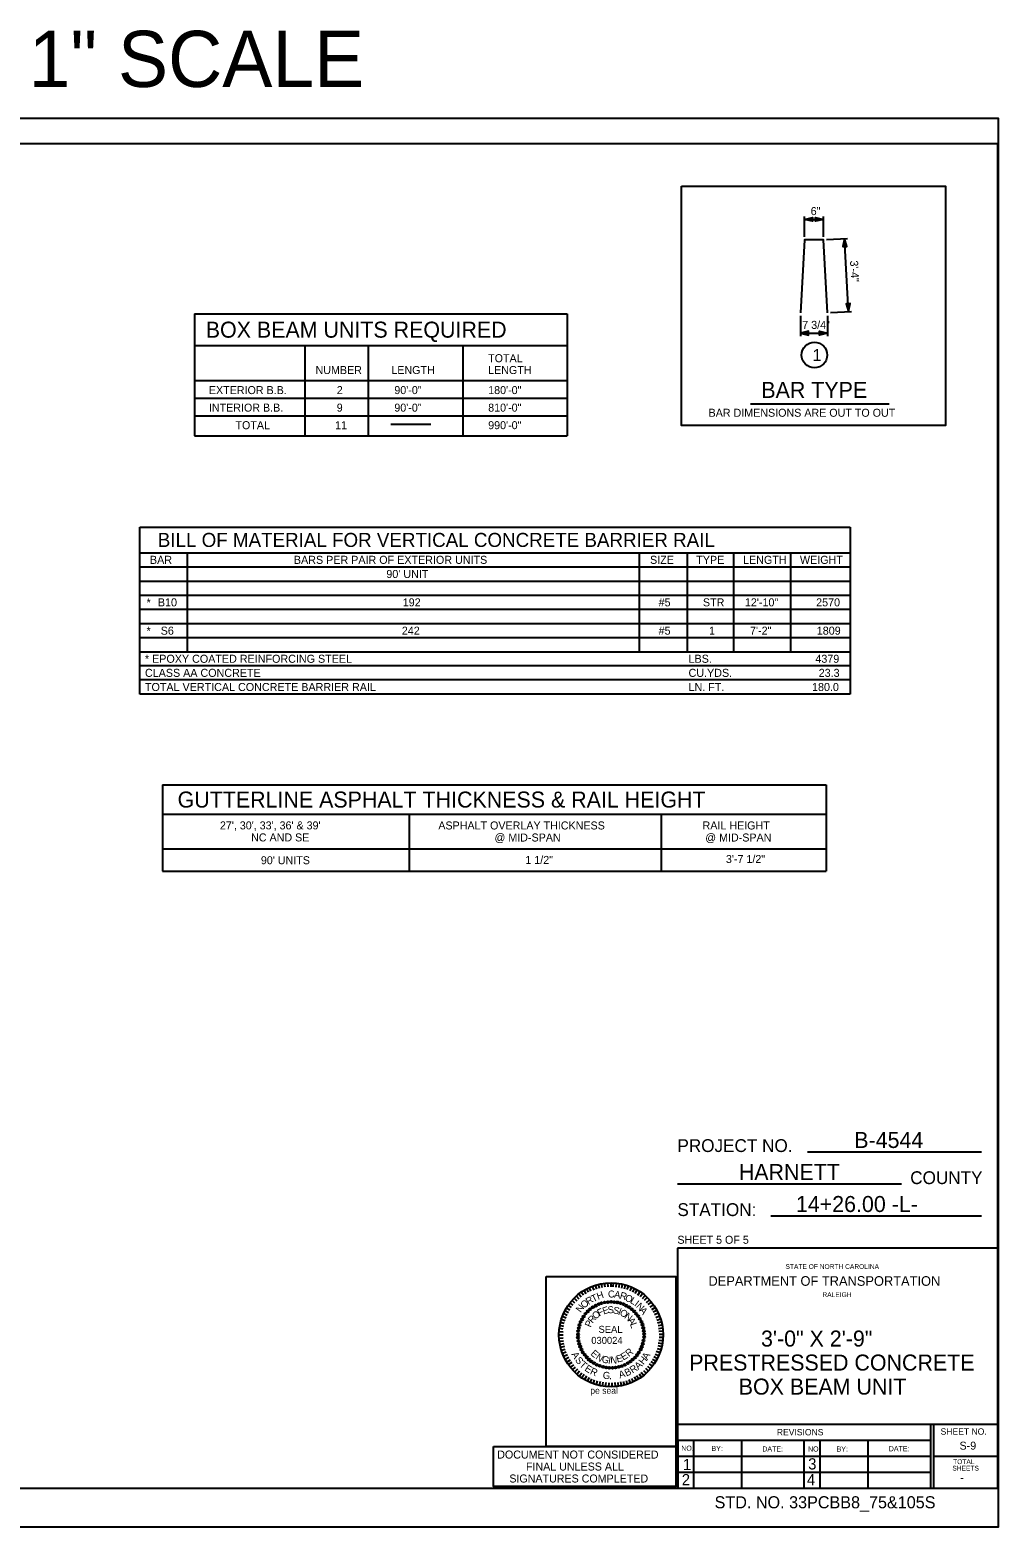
# Model space of a CAD drawing. Extents: x -38 to 94, y -165 to 80.
# Drawn here: x 72.87 to 88, y -165.04 to -141.66 of the extents above; entities that cross this region are included whole.
import ezdxf

# ---------------------------------------------------------------- set-up
doc = ezdxf.new("R2010")
doc.units = 0
for name, color, linetype in [('Arrowhead Terminators', 7, 'Continuous'), ('Arrowhead Terminators CELL', 7, 'Continuous'), ('Dimension Lines', 7, 'Continuous'), ('Peseal', 7, 'Continuous'), ('Plan Sheet', 7, 'Continuous'), ('Plan Sheet CELL', 7, 'Continuous'), ('Plot Shape CELL', 7, 'Continuous'), ('Rebar Lines', 7, 'Continuous'), ('Sheet Sticker Exception Certification CELL', 7, 'Continuous'), ('Subtitle Text', 7, 'Continuous'), ('Text', 7, 'Continuous'), ('Title Text', 7, 'Continuous'), ('User Information Notes', 7, 'Continuous'), ('User Information Notes CELL', 7, 'Continuous')]:
    doc.layers.add(name, color=color, linetype=linetype)

msp = doc.modelspace()

# ---------------------------------------------------------------- linework, layer by layer
at = {"layer": 'Arrowhead Terminators'}
for points in [[(84.973, -144.616), (85.098, -144.585), (85.098, -144.647)], [(85.27, -144.616), (85.145, -144.647), (85.145, -144.585)], [(84.911, -146.393), (85.036, -146.425), (85.036, -146.362)], [(85.333, -146.393), (85.208, -146.425), (85.208, -146.362)]]:
    msp.add_lwpolyline(points, close=True, dxfattribs=at)
at = {"layer": 'Arrowhead Terminators CELL'}
for points in [[(85.596, -144.916), (85.572, -145.042), (85.634, -145.039)], [(85.659, -146.056), (85.683, -145.93), (85.621, -145.933)]]:
    msp.add_lwpolyline(points, close=True, dxfattribs=at)
at = {"layer": 'Dimension Lines'}
for p, q in [((84.973, -144.888), (84.973, -144.571)), ((84.973, -144.616), (85.27, -144.616)), ((85.27, -144.888), (85.27, -144.571)), ((85.316, -144.931), (85.642, -144.913)), ((85.659, -146.056), (85.596, -144.916)), ((85.379, -146.072), (85.705, -146.054)), ((84.911, -146.122), (84.911, -146.439)), ((85.333, -146.122), (85.333, -146.439)), ((84.911, -146.393), (85.333, -146.393))]:
    msp.add_line(p, q, dxfattribs=at)
at = {"layer": 'Peseal'}
for p, q in [((81.598, -161.372), (81.571, -161.318)), ((81.637, -161.353), (81.614, -161.298)), ((81.684, -161.337), (81.661, -161.279)), ((81.727, -161.321), (81.708, -161.259)), ((81.77, -161.31), (81.755, -161.247)), ((81.813, -161.298), (81.801, -161.236)), ((81.856, -161.294), (81.848, -161.232)), ((81.903, -161.286), (81.899, -161.224)), ((81.95, -161.286), (81.95, -161.224)), ((81.985, -161.286), (81.989, -161.224)), ((82.028, -161.29), (82.036, -161.228)), ((82.075, -161.298), (82.083, -161.236)), ((82.118, -161.306), (82.13, -161.243)), ((82.161, -161.318), (82.176, -161.255)), ((82.204, -161.329), (82.227, -161.271)), ((82.247, -161.349), (82.274, -161.29)), ((82.29, -161.368), (82.317, -161.31)), ((81.356, -161.575), (81.309, -161.54)), ((81.387, -161.54), (81.341, -161.501)), ((81.419, -161.509), (81.372, -161.462)), ((81.45, -161.478), (81.411, -161.431)), ((81.485, -161.446), (81.446, -161.4)), ((81.52, -161.419), (81.485, -161.368)), ((81.559, -161.396), (81.528, -161.341)), ((82.329, -161.388), (82.36, -161.333)), ((82.368, -161.415), (82.403, -161.361)), ((82.403, -161.439), (82.442, -161.392)), ((82.442, -161.47), (82.481, -161.423)), ((82.473, -161.497), (82.516, -161.454)), ((82.505, -161.532), (82.551, -161.489)), ((82.532, -161.564), (82.583, -161.525)), ((81.247, -161.775), (81.188, -161.751)), ((81.266, -161.732), (81.208, -161.704)), ((81.286, -161.693), (81.227, -161.661)), ((81.305, -161.65), (81.251, -161.618)), ((81.333, -161.611), (81.278, -161.575)), ((82.563, -161.603), (82.614, -161.568)), ((82.587, -161.638), (82.637, -161.607)), ((82.61, -161.677), (82.665, -161.65)), ((82.63, -161.72), (82.684, -161.693)), ((82.649, -161.763), (82.708, -161.739)), ((81.2, -161.993), (81.137, -161.989)), ((81.204, -161.947), (81.145, -161.939)), ((81.212, -161.904), (81.149, -161.892)), ((81.219, -161.861), (81.161, -161.845)), ((81.231, -161.818), (81.173, -161.798)), ((82.665, -161.806), (82.723, -161.786)), ((82.676, -161.849), (82.735, -161.833)), ((82.684, -161.892), (82.747, -161.88)), ((82.692, -161.935), (82.755, -161.927)), ((82.696, -161.978), (82.759, -161.974)), ((81.2, -162.04), (81.137, -162.04)), ((81.2, -162.087), (81.137, -162.091)), ((81.208, -162.134), (81.145, -162.142)), ((81.212, -162.177), (81.153, -162.189)), ((81.223, -162.22), (81.161, -162.236)), ((82.669, -162.247), (82.731, -162.267)), ((82.68, -162.204), (82.743, -162.22)), ((82.688, -162.161), (82.751, -162.173)), ((82.696, -162.118), (82.759, -162.126)), ((82.7, -162.025), (82.762, -162.025)), ((82.7, -162.072), (82.762, -162.075)), ((81.235, -162.263), (81.176, -162.282)), ((81.251, -162.306), (81.192, -162.329)), ((81.27, -162.349), (81.212, -162.376)), ((81.29, -162.388), (81.231, -162.419)), ((81.313, -162.431), (81.259, -162.462)), ((81.337, -162.466), (81.286, -162.501)), ((82.571, -162.454), (82.626, -162.489)), ((82.598, -162.415), (82.653, -162.447)), ((82.618, -162.376), (82.676, -162.404)), ((82.637, -162.337), (82.696, -162.361)), ((82.657, -162.29), (82.716, -162.314)), ((81.364, -162.505), (81.313, -162.544)), ((81.391, -162.54), (81.348, -162.579)), ((81.426, -162.572), (81.38, -162.618)), ((81.458, -162.603), (81.419, -162.65)), ((81.493, -162.634), (81.458, -162.681)), ((81.528, -162.657), (81.493, -162.708)), ((81.567, -162.681), (81.536, -162.736)), ((81.606, -162.704), (81.579, -162.759)), ((82.27, -162.716), (82.298, -162.771)), ((82.309, -162.693), (82.341, -162.751)), ((82.348, -162.669), (82.384, -162.724)), ((82.387, -162.646), (82.423, -162.697)), ((82.423, -162.618), (82.462, -162.669)), ((82.458, -162.591), (82.497, -162.634)), ((82.489, -162.556), (82.536, -162.603)), ((82.52, -162.525), (82.567, -162.568)), ((82.548, -162.489), (82.598, -162.529)), ((81.645, -162.724), (81.622, -162.779)), ((81.688, -162.739), (81.669, -162.798)), ((81.735, -162.755), (81.716, -162.814)), ((81.778, -162.767), (81.762, -162.825)), ((81.821, -162.775), (81.809, -162.837)), ((81.868, -162.782), (81.86, -162.845)), ((81.915, -162.786), (81.911, -162.849)), ((81.962, -162.786), (81.962, -162.849)), ((82.009, -162.782), (82.012, -162.845)), ((82.055, -162.779), (82.063, -162.841)), ((82.098, -162.771), (82.11, -162.833)), ((82.141, -162.763), (82.157, -162.822)), ((82.184, -162.747), (82.204, -162.81)), ((82.227, -162.732), (82.251, -162.79))]:
    msp.add_line(p, q, dxfattribs=at)
for centre, radius in [((81.757, -161.558), 0.0149), ((81.801, -161.542), 0.0142), ((81.85, -161.53), 0.0138), ((81.901, -161.525), 0.0157), ((81.95, -161.521), 0.0156), ((81.999, -161.525), 0.0157), ((82.048, -161.529), 0.0161), ((82.098, -161.542), 0.0142), ((82.143, -161.558), 0.0149), ((81.499, -161.794), 0.018), ((81.522, -161.749), 0.0168), ((81.55, -161.706), 0.0138), ((81.587, -161.669), 0.0166), ((81.624, -161.636), 0.0168), ((81.667, -161.605), 0.0168), ((81.712, -161.579), 0.0175), ((82.188, -161.581), 0.0157), ((82.231, -161.605), 0.0157), ((82.272, -161.634), 0.0153), ((82.311, -161.669), 0.0153), ((82.344, -161.706), 0.0153), ((82.374, -161.743), 0.0157), ((82.401, -161.786), 0.0157), ((81.434, -162.029), 0.0156), ((81.438, -161.98), 0.0157), ((81.446, -161.931), 0.0161), ((81.458, -161.882), 0.0167), ((81.475, -161.835), 0.0149), ((82.425, -161.831), 0.0149), ((82.442, -161.878), 0.0167), ((82.454, -161.927), 0.0161), ((82.462, -161.976), 0.0157), ((82.466, -162.025), 0.0156), ((81.434, -162.077), 0.0157), ((81.442, -162.128), 0.0157), ((81.454, -162.177), 0.0161), ((81.469, -162.222), 0.0167), ((81.489, -162.267), 0.0175), ((82.413, -162.263), 0.0157), ((82.43, -162.222), 0.0167), ((82.446, -162.173), 0.0161), ((82.458, -162.124), 0.0157), ((82.466, -162.073), 0.0157), ((81.51, -162.31), 0.0157), ((81.54, -162.347), 0.0153), ((81.571, -162.388), 0.0166), ((81.606, -162.423), 0.0166), ((81.643, -162.452), 0.0168), ((81.684, -162.48), 0.0157), ((82.212, -162.48), 0.0157), ((82.253, -162.454), 0.0153), ((82.288, -162.423), 0.0153), ((82.325, -162.39), 0.0153), ((82.358, -162.351), 0.0168), ((82.385, -162.31), 0.0157), ((81.729, -162.503), 0.0149), ((81.776, -162.521), 0.0167), ((81.825, -162.536), 0.0161), ((81.874, -162.548), 0.0157), ((81.923, -162.552), 0.0156), ((81.973, -162.552), 0.0156), ((82.022, -162.548), 0.0157), ((82.071, -162.536), 0.0161), ((82.12, -162.523), 0.0149), ((82.165, -162.505), 0.0175)]:
    msp.add_circle(centre, radius, dxfattribs=at)
at = {"layer": 'Plan Sheet'}
for p, q in [((75.444, -146.092), (81.263, -146.092)), ((75.444, -146.092), (75.444, -147.995)), ((81.263, -146.092), (81.263, -147.995)), ((75.444, -146.586), (81.263, -146.586)), ((77.169, -146.586), (77.169, -147.995)), ((78.154, -146.586), (78.154, -147.995)), ((79.634, -146.586), (79.634, -147.995)), ((75.444, -147.134), (81.263, -147.134)), ((75.444, -147.408), (81.263, -147.408)), ((75.444, -147.682), (81.263, -147.682)), ((75.444, -147.995), (81.263, -147.995)), ((74.59, -152.031), (74.59, -149.423)), ((74.59, -149.423), (85.685, -149.423)), ((85.685, -149.423), (85.685, -152.031)), ((74.59, -149.822), (85.685, -149.822)), ((75.327, -149.822), (75.327, -151.368)), ((82.39, -149.822), (82.39, -151.368)), ((83.137, -149.822), (83.137, -151.368)), ((83.137, -149.822), (83.137, -151.147)), ((83.861, -149.822), (83.861, -151.368)), ((83.861, -149.822), (83.861, -151.147)), ((84.753, -149.822), (84.753, -151.368)), ((74.59, -150.043), (85.685, -150.043)), ((74.59, -150.264), (85.685, -150.264)), ((74.59, -150.485), (85.685, -150.485)), ((74.59, -150.706), (85.685, -150.706)), ((74.59, -150.926), (85.685, -150.926)), ((74.59, -151.147), (85.685, -151.147)), ((74.59, -151.368), (82.383, -151.368)), ((74.59, -151.368), (85.685, -151.368)), ((85.685, -151.588), (74.59, -151.588)), ((85.685, -151.809), (74.59, -151.809)), ((85.685, -152.031), (74.59, -152.031)), ((74.945, -153.449), (85.313, -153.449)), ((74.945, -153.449), (74.945, -154.797)), ((85.313, -153.449), (85.313, -154.797)), ((74.945, -153.905), (85.313, -153.905)), ((78.799, -153.905), (78.799, -154.797)), ((82.731, -153.905), (82.731, -154.797)), ((74.945, -154.447), (85.313, -154.447)), ((74.945, -154.797), (85.313, -154.797)), ((74.945, -154.797), (85.313, -154.797))]:
    msp.add_line(p, q, dxfattribs=at)
msp.add_lwpolyline([(83.053, -144.099), (87.174, -144.099), (87.174, -147.838), (83.053, -147.838)], close=True, dxfattribs=at)
at = {"layer": 'Plan Sheet CELL'}
for p, q in [((87.996, -143.038), (87.996, -143.038)), ((55.987, -143.432), (87.987, -143.432)), ((87.987, -143.432), (87.987, -164.432)), ((87.737, -159.181), (85.02, -159.181)), ((86.487, -159.682), (82.987, -159.682)), ((87.737, -160.181), (84.448, -160.181)), ((87.987, -160.681), (82.987, -160.681)), ((82.987, -160.681), (82.987, -164.432)), ((82.987, -163.431), (87.987, -163.431)), ((86.938, -163.431), (86.938, -164.432)), ((86.988, -163.431), (86.988, -164.432)), ((82.987, -163.681), (86.939, -163.681)), ((82.991, -163.681), (82.991, -164.432)), ((83.237, -163.681), (83.237, -164.432)), ((83.987, -163.685), (83.987, -164.435)), ((84.963, -163.681), (84.963, -164.438)), ((85.214, -163.681), (85.214, -164.432)), ((85.963, -163.681), (85.963, -164.432)), ((82.987, -163.931), (86.948, -163.931)), ((86.988, -163.931), (87.979, -163.931)), ((82.987, -164.181), (86.939, -164.181)), ((55.987, -164.432), (87.987, -164.432)), ((87.996, -165.038), (87.996, -165.038))]:
    msp.add_line(p, q, dxfattribs=at)
at = {"layer": 'Plot Shape CELL'}
msp.add_lwpolyline([(54.933, -143.038), (87.996, -143.038), (87.996, -165.038), (54.933, -165.038)], close=True, dxfattribs=at)
at = {"layer": 'Rebar Lines'}
msp.add_lwpolyline([(85.333, -146.076), (85.27, -144.934), (84.973, -144.934), (84.911, -146.076)], dxfattribs=at)
at = {"layer": 'Sheet Sticker Exception Certification CELL'}
msp.add_lwpolyline([(80.114, -163.78), (82.962, -163.78), (82.962, -164.407), (80.114, -164.407)], close=True, dxfattribs=at)
at = {"layer": 'Text'}
msp.add_line((78.51, -147.816), (79.134, -147.816), dxfattribs=at)
msp.add_circle((85.127, -146.735), 0.2, dxfattribs=at)
at = {"layer": 'Title Text'}
msp.add_line((84.131, -147.498), (86.297, -147.498), dxfattribs=at)
at = {"layer": 'User Information Notes'}
msp.add_line((81.95, -162.036), (81.95, -162.036), dxfattribs=at)
at = {"layer": 'User Information Notes CELL'}
msp.add_line((81.95, -162.036), (81.95, -162.036), dxfattribs=at)
msp.add_lwpolyline([(80.937, -161.124), (82.962, -161.124), (82.962, -163.78), (80.937, -163.78)], close=True, dxfattribs=at)
msp.add_circle((81.95, -162.036), 0.813, dxfattribs=at)

# ---------------------------------------------------------------- texts
at = {"layer": 'Peseal'}
for s, height, rotation, p in [('O', 0.109, 39.9967, (81.528, -161.63)), ('R', 0.109, 32.9699, (81.598, -161.571)), ('T', 0.109, 25.943, (81.673, -161.529)), ('H', 0.109, 18.9162, (81.747, -161.489)), ('C', 0.109, 4.8625, (81.907, -161.458)), ('A', 0.109, 350.8088, (81.993, -161.454)), ('R', 0.109, 343.7819, (82.079, -161.466)), ('O', 0.109, 336.7551, (82.157, -161.497)), ('L', 0.109, 329.7282, (82.239, -161.532)), ('I', 0.109, 322.7014, (82.305, -161.575)), ('N', 0.109, 315.6745, (82.333, -161.599)), ('N', 0.109, 54.0504, (81.477, -161.697)), ('R', 0.109, 50.5765, (81.661, -161.864)), ('O', 0.109, 42.5436, (81.712, -161.802)), ('F', 0.109, 26.4777, (81.766, -161.751)), ('E', 0.109, 18.4448, (81.837, -161.72)), ('S', 0.109, 2.3789, (81.899, -161.7)), ('S', 0.109, 346.313, (81.973, -161.697)), ('I', 0.109, 338.28, (82.051, -161.716)), ('O', 0.109, 330.2471, (82.075, -161.72)), ('N', 0.109, 322.2141, (82.149, -161.767)), ('A', 0.109, 306.1483, (82.204, -161.814)), ('A', 0.109, 308.6477, (82.387, -161.657)), ('P', 0.109, 66.6424, (81.634, -161.927)), ('L', 0.109, 290.0824, (82.243, -161.868)), ('R', 0.109, 38.6997, (82.227, -162.384)), ('A', 0.111, 300.3993, (81.325, -162.34)), ('S', 0.111, 309.4349, (81.381, -162.434)), ('T', 0.111, 318.1096, (81.447, -162.515)), ('E', 0.109, 318.5179, (81.622, -162.341)), ('N', 0.109, 326.5361, (81.7, -162.407)), ('G', 0.109, 342.5725, (81.794, -162.458)), ('I', 0.109, 350.5906, (81.899, -162.482)), ('N', 0.109, 358.6088, (81.938, -162.482)), ('E', 0.109, 14.6452, (82.048, -162.47)), ('E', 0.109, 30.6815, (82.141, -162.439)), ('A', 0.111, 42.3241, (82.376, -162.585)), ('H', 0.111, 51.3597, (82.457, -162.511)), ('A', 0.111, 59.6007, (82.519, -162.434)), ('E', 0.111, 327.1453, (81.528, -162.588)), ('R', 0.111, 335.458, (81.613, -162.643)), ('G', 0.111, 353.3858, (81.816, -162.718)), ('.', 0.111, 2.1323, (81.921, -162.73)), ('A', 0.111, 15.7955, (82.086, -162.717)), ('B', 0.111, 24.8312, (82.191, -162.688)), ('R', 0.111, 33.5776, (82.287, -162.643))]:
    msp.add_text(s, height=height, rotation=rotation, dxfattribs=at).set_placement(p)
for s, p in [('SEAL', (81.755, -162.005)), ('030024', (81.642, -162.177))]:
    msp.add_text(s, height=0.1094, dxfattribs=at).set_placement(p)
at = {"layer": 'Plan Sheet CELL'}
for s, height, p in [('PROJECT NO.', 0.2, (82.987, -159.181)), ('COUNTY', 0.2, (86.624, -159.682)), ('STATION:', 0.2, (82.987, -160.181)), ('SHEET 5 OF 5', 0.125, (82.987, -160.614)), ('STATE OF NORTH CAROLINA', 0.07499, (84.675, -161.007)), ('DEPARTMENT OF TRANSPORTATION', 0.14999, (83.472, -161.27)), ('RALEIGH', 0.075, (85.252, -161.446)), ('REVISIONS', 0.1, (84.54, -163.606)), ('SHEET NO.', 0.1, (87.098, -163.596)), ('NO.', 0.0797, (83.047, -163.846)), ('BY:', 0.0797, (83.519, -163.85)), ('DATE:', 0.0797, (84.313, -163.858)), ('NO.', 0.0797, (85.027, -163.858)), ('BY:', 0.0797, (85.473, -163.859)), ('DATE:', 0.0797, (86.289, -163.854)), ('1', 0.175, (83.073, -164.148)), ('3', 0.175, (85.029, -164.139)), ('SHEETS', 0.075, (87.282, -164.156)), ('TOTAL', 0.075, (87.294, -164.055)), ('2', 0.175, (83.055, -164.385)), ('4', 0.175, (85.01, -164.385))]:
    msp.add_text(s, height=height, dxfattribs=at).set_placement(p)
at = {"layer": 'Sheet Sticker Exception Certification CELL'}
for s, p in [('DOCUMENT NOT CONSIDERED', (80.172, -163.968)), ('FINAL UNLESS ALL', (80.621, -164.155)), ('SIGNATURES COMPLETED', (80.361, -164.342))]:
    msp.add_text(s, height=0.12472, dxfattribs=at).set_placement(p)
at = {"layer": 'Subtitle Text'}
for s, height, p in [('BOX BEAM UNITS REQUIRED', 0.25, (75.619, -146.464)), ('3\'-0" X 2\'-9"', 0.25, (84.293, -162.219)), ('PRESTRESSED CONCRETE', 0.25, (83.17, -162.594)), ('BOX BEAM UNIT', 0.25, (83.945, -162.969)), ('STD. NO. 33PCBB8_75&105S', 0.18869, (83.568, -164.745))]:
    msp.add_text(s, height=height, dxfattribs=at).set_placement(p)
at = {"layer": 'Text'}
for s, rotation, p in [('6"', 360, (85.069, -144.55)), ('3\'-4"', 273.139, (85.683, -145.262)), ('7 3/4"', 360, (84.937, -146.327))]:
    msp.add_text(s, height=0.1255, rotation=rotation, dxfattribs=at).set_placement(p)
for s, height, p in [('TOTAL', 0.125, (80.03, -146.847)), ('1', 0.188, (85.098, -146.829)), ('NUMBER', 0.125, (77.334, -147.032)), ('LENGTH', 0.125, (78.518, -147.032)), ('LENGTH', 0.125, (80.03, -147.032)), ('EXTERIOR B.B.', 0.125, (75.668, -147.345)), ('2', 0.125, (77.666, -147.345)), ('90\'-0"', 0.125, (78.565, -147.345)), ('180\'-0"', 0.125, (80.031, -147.345)), ('INTERIOR B.B.', 0.125, (75.668, -147.619)), ('9', 0.125, (77.665, -147.619)), ('90\'-0"', 0.125, (78.565, -147.619)), ('810\'-0"', 0.125, (80.031, -147.619)), ('BAR DIMENSIONS ARE OUT TO OUT', 0.125, (83.474, -147.699)), ('TOTAL', 0.125, (76.083, -147.893)), ('11', 0.125, (77.64, -147.893)), ('990\'-0"', 0.125, (80.031, -147.893)), ('BILL OF MATERIAL FOR VERTICAL CONCRETE BARRIER RAIL', 0.2193, (74.87, -149.732)), ('BAR', 0.1255, (74.747, -149.996)), ('BARS PER PAIR OF EXTERIOR UNITS', 0.12546, (76.996, -149.996)), ("90' UNIT", 0.1255, (78.44, -150.217)), ('SIZE', 0.1255, (82.559, -149.996)), ('TYPE', 0.1255, (83.281, -149.996)), ('LENGTH', 0.1255, (84.012, -149.996)), ('WEIGHT', 0.1255, (84.901, -149.996)), ('*', 0.125, (74.695, -150.662)), ('B10', 0.1255, (74.871, -150.66)), ('192', 0.1255, (78.696, -150.66)), ('#5', 0.1255, (82.693, -150.66)), ('STR', 0.1255, (83.385, -150.66)), ('12\'-10"', 0.1255, (84.041, -150.66)), ('2570', 0.1255, (85.154, -150.66)), ('*', 0.125, (74.695, -151.104)), ('S6', 0.1255, (74.915, -151.102)), ('242', 0.1255, (78.682, -151.102)), ('#5', 0.1255, (82.693, -151.102)), ('1', 0.125, (83.481, -151.102)), ('7\'-2"', 0.1255, (84.121, -151.102)), ('1809', 0.1255, (85.164, -151.102)), ('* EPOXY COATED REINFORCING STEEL', 0.12546, (74.669, -151.541)), ('LBS. ', 0.1255, (83.161, -151.541)), ('4379', 0.1255, (85.142, -151.541)), ('CLASS AA CONCRETE', 0.12546, (74.669, -151.761)), ('CU.YDS.', 0.1255, (83.161, -151.761)), ('23.3', 0.1255, (85.194, -151.761)), ('TOTAL VERTICAL CONCRETE BARRIER RAIL', 0.12546, (74.669, -151.982)), ('LN. FT.', 0.1255, (83.161, -151.982)), ('180.0', 0.1255, (85.09, -151.982)), ('GUTTERLINE ASPHALT THICKNESS & RAIL HEIGHT', 0.25, (75.179, -153.802)), ('ASPHALT OVERLAY THICKNESS', 0.125, (79.252, -154.144)), ('RAIL HEIGHT', 0.125, (83.38, -154.144)), ('@ MID-SPAN', 0.125, (80.13, -154.332)), ('@ MID-SPAN', 0.125, (83.422, -154.332)), ('3\'-7 1/2"', 0.125, (83.745, -154.668)), ("90' UNITS", 0.125, (76.48, -154.687)), ('1 1/2"', 0.125, (80.612, -154.682)), ('S-9', 0.125, (87.394, -163.829)), ('-', 0.125, (87.403, -164.329))]:
    msp.add_text(s, height=height, dxfattribs=at).set_placement(p)
at = {"layer": 'Title Text'}
for s, p in [('BAR TYPE', (84.298, -147.405)), ('B-4544', (85.75, -159.118)), ('HARNETT', (83.946, -159.619)), ('14+26.00 -L-', (84.838, -160.118))]:
    msp.add_text(s, height=0.25, dxfattribs=at).set_placement(p)
at = {"layer": 'User Information Notes'}
for s, height, p in [('1" SCALE', 0.8772, (72.853, -142.549)), ("27', 30', 33', 36' & 39' ", 0.125, (75.84, -154.143)), ('   NC AND SE', 0.125, (76.188, -154.331))]:
    msp.add_text(s, height=height, dxfattribs=at).set_placement(p)
at = {"layer": 'User Information Notes CELL'}
msp.add_text('pe seal', height=0.1, dxfattribs=at).set_placement((81.626, -162.956))

doc.saveas('drawing.dxf')
